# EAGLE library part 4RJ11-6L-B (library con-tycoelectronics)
CORCOM Modular RJ Jacks L - Ganged Series Source: www.tycoelectronics.com .. ENG_DS_1654001_1099_RJ_L_0507.pdf
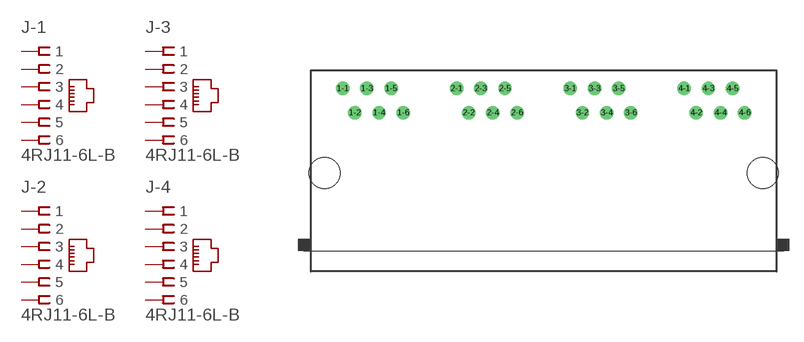
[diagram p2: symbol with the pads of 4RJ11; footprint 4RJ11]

Designator prefix J; gates -1=JACK6 -2=JACK6 -3=JACK6 -4=JACK6

## 4RJ11-6L-B (MF: TYCO ELECTRONICS; MPN: 4RJ11-6L-B; OC_FARNELL: unknown; OC_NEWARK: 48F3956)  [4RJ11]
1-1  -1:1  pas
1-2  -1:2  pas
1-3  -1:3  pas
1-4  -1:4  pas
1-5  -1:5  pas
1-6  -1:6  pas
2-1  -2:1  pas
2-2  -2:2  pas
2-3  -2:3  pas
2-4  -2:4  pas
2-5  -2:5  pas
2-6  -2:6  pas
3-1  -3:1  pas
3-2  -3:2  pas
3-3  -3:3  pas
3-4  -3:4  pas
3-5  -3:5  pas
3-6  -3:6  pas
4-1  -4:1  pas
4-2  -4:2  pas
4-3  -4:3  pas
4-4  -4:4  pas
4-5  -4:5  pas
4-6  -4:6  pas

## Footprint 4RJ11 (pad centres in mm)
RJ11 x 4 Source: www.tycoelectronics.com .. ENG_DS_1654001_1099_RJ_L_0507.pdf
drill 0.9 pad 1.4 round: 1-1 -21.082,8.89; 1-2 -19.812,6.35; 1-3 -18.542,8.89; 1-4 -17.272,6.35; 1-5 -16.002,8.89; 1-6 -14.732,6.35; 2-1 -9.144,8.89; 2-2 -7.874,6.35; 2-3 -6.604,8.89; 2-4 -5.334,6.35; 2-5 -4.064,8.89; 2-6 -2.794,6.35; 3-1 2.794,8.89; 3-2 4.064,6.35; 3-3 5.334,8.89; 3-4 6.604,6.35; 3-5 7.874,8.89; 3-6 9.144,6.35; 4-1 14.732,8.89; 4-2 16.002,6.35; 4-3 17.272,8.89; 4-4 18.542,6.35; 4-5 19.812,8.89; 4-6 21.082,6.35
hole 3.251 at -22.987,0
hole 3.251 at 22.987,0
